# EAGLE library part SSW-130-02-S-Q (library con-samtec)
THROUGH-HOLE .025" SQ POST SOCKET Source: Samtec SSW.pdf
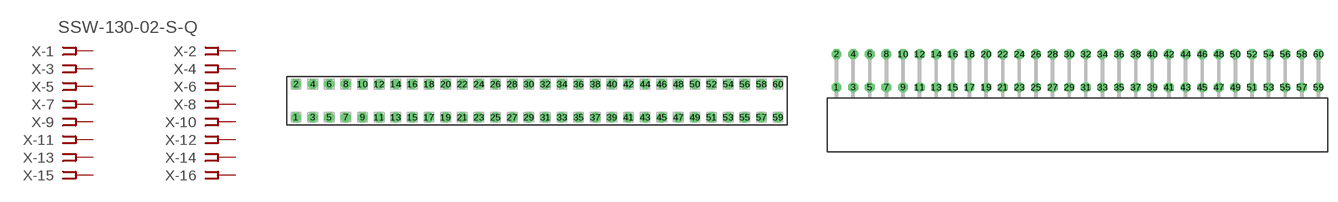
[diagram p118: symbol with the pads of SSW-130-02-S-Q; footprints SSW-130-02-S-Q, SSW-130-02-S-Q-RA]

Designator prefix X; gates -1=FPINV -2=FPIN -3=FPIN -4=FPIN -5=FPIN -6=FPIN -7=FPIN -8=FPIN -9=FPIN -10=FPIN -11=FPIN -12=FPIN -13=FPIN -14=FPIN -15=FPIN -16=FPIN -17=FPIN -18=FPIN -19=FPIN -20=FPIN -21=FPIN -22=FPIN -23=FPIN -24=FPIN -25=FPIN -26=FPIN -27=FPIN -28=FPIN -29=FPIN -30=FPIN -31=FPIN -32=FPIN -33=FPIN -34=FPIN -35=FPIN -36=FPIN -37=FPIN -38=FPIN -39=FPIN -40=FPIN -41=FPIN -42=FPIN -43=FPIN -44=FPIN -45=FPIN -46=FPIN -47=FPIN -48=FPIN -49=FPIN -50=FPIN -51=FPIN -52=FPIN -53=FPIN -54=FPIN -55=FPIN -56=FPIN -57=FPIN -58=FPIN -59=FPIN -60=FPIN

## SSW-130-02-S-Q (MPN: SSW-130-02-S-Q; OC_FARNELL: unknown; OC_NEWARK: 83P0024)  [SSW-130-02-S-Q]
1  -1:1  pas
2  -2:1  pas
3  -3:1  pas
4  -4:1  pas
5  -5:1  pas
6  -6:1  pas
7  -7:1  pas
8  -8:1  pas
9  -9:1  pas
10  -10:1  pas
11  -11:1  pas
12  -12:1  pas
13  -13:1  pas
14  -14:1  pas
15  -15:1  pas
16  -16:1  pas
17  -17:1  pas
18  -18:1  pas
19  -19:1  pas
20  -20:1  pas
21  -21:1  pas
22  -22:1  pas
23  -23:1  pas
24  -24:1  pas
25  -25:1  pas
26  -26:1  pas
27  -27:1  pas
28  -28:1  pas
29  -29:1  pas
30  -30:1  pas
31  -31:1  pas
32  -32:1  pas
33  -33:1  pas
34  -34:1  pas
35  -35:1  pas
36  -36:1  pas
37  -37:1  pas
38  -38:1  pas
39  -39:1  pas
40  -40:1  pas
41  -41:1  pas
42  -42:1  pas
43  -43:1  pas
44  -44:1  pas
45  -45:1  pas
46  -46:1  pas
47  -47:1  pas
48  -48:1  pas
49  -49:1  pas
50  -50:1  pas
51  -51:1  pas
52  -52:1  pas
53  -53:1  pas
54  -54:1  pas
55  -55:1  pas
56  -56:1  pas
57  -57:1  pas
58  -58:1  pas
59  -59:1  pas
60  -60:1  pas

## SSW-130-02-S-QRA (MPN: SSW-130-02-S-Q-RA; OC_FARNELL: unknown; OC_NEWARK: 83P0025)  [SSW-130-02-S-Q-RA]
Pads as for SSW-130-02-S-Q

## Footprint SSW-130-02-S-Q (pad centres in mm)
THROUGH-HOLE .025" SQ POST SOCKET Source: Samtec SSW.pdf
drill 1 pad 1.5 octagon: 1 -36.83,-2.54; 2 -36.83,2.54; 3 -34.29,-2.54; 4 -34.29,2.54; 5 -31.75,-2.54; 6 -31.75,2.54; 7 -29.21,-2.54; 8 -29.21,2.54; 9 -26.67,-2.54; 10 -26.67,2.54; 11 -24.13,-2.54; 12 -24.13,2.54; 13 -21.59,-2.54; 14 -21.59,2.54; 15 -19.05,-2.54; 16 -19.05,2.54; 17 -16.51,-2.54; 18 -16.51,2.54; 19 -13.97,-2.54; 20 -13.97,2.54; 21 -11.43,-2.54; 22 -11.43,2.54; 23 -8.89,-2.54; 24 -8.89,2.54; 25 -6.35,-2.54; 26 -6.35,2.54; 27 -3.81,-2.54; 28 -3.81,2.54; 29 -1.27,-2.54; 30 -1.27,2.54; 31 1.27,-2.54; 32 1.27,2.54; 33 3.81,-2.54; 34 3.81,2.54; 35 6.35,-2.54; 36 6.35,2.54; 37 8.89,-2.54; 38 8.89,2.54; 39 11.43,-2.54; 40 11.43,2.54; 41 13.97,-2.54; 42 13.97,2.54; 43 16.51,-2.54; 44 16.51,2.54; 45 19.05,-2.54; 46 19.05,2.54; 47 21.59,-2.54; 48 21.59,2.54; 49 24.13,-2.54; 50 24.13,2.54; 51 26.67,-2.54; 52 26.67,2.54; 53 29.21,-2.54; 54 29.21,2.54; 55 31.75,-2.54; 56 31.75,2.54; 57 34.29,-2.54; 58 34.29,2.54; 59 36.83,-2.54; 60 36.83,2.54

## Footprint SSW-130-02-S-Q-RA (pad centres in mm)
THROUGH-HOLE .025" SQ POST SOCKET Source: Samtec SSW.pdf
drill 1 pad 1.5 octagon: 1 -36.83,1.524; 2 -36.83,6.604; 3 -34.29,1.524; 4 -34.29,6.604; 5 -31.75,1.524; 6 -31.75,6.604; 7 -29.21,1.524; 8 -29.21,6.604; 9 -26.67,1.524; 10 -26.67,6.604; 11 -24.13,1.524; 12 -24.13,6.604; 13 -21.59,1.524; 14 -21.59,6.604; 15 -19.05,1.524; 16 -19.05,6.604; 17 -16.51,1.524; 18 -16.51,6.604; 19 -13.97,1.524; 20 -13.97,6.604; 21 -11.43,1.524; 22 -11.43,6.604; 23 -8.89,1.524; 24 -8.89,6.604; 25 -6.35,1.524; 26 -6.35,6.604; 27 -3.81,1.524; 28 -3.81,6.604; 29 -1.27,1.524; 30 -1.27,6.604; 31 1.27,1.524; 32 1.27,6.604; 33 3.81,1.524; 34 3.81,6.604; 35 6.35,1.524; 36 6.35,6.604; 37 8.89,1.524; 38 8.89,6.604; 39 11.43,1.524; 40 11.43,6.604; 41 13.97,1.524; 42 13.97,6.604; 43 16.51,1.524; 44 16.51,6.604; 45 19.05,1.524; 46 19.05,6.604; 47 21.59,1.524; 48 21.59,6.604; 49 24.13,1.524; 50 24.13,6.604; 51 26.67,1.524; 52 26.67,6.604; 53 29.21,1.524; 54 29.21,6.604; 55 31.75,1.524; 56 31.75,6.604; 57 34.29,1.524; 58 34.29,6.604; 59 36.83,1.524; 60 36.83,6.604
